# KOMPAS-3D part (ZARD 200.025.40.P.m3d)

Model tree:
1. Поверхность без истории:1
2. Поверхность без истории:2
3. Поверхность без истории:3
4. Поверхность без истории:4
5. Поверхность без истории:5
6. Поверхность без истории:6
7. Поверхность без истории:7
8. Поверхность без истории:8
9. Поверхность без истории:9
10. Поверхность без истории:10
11. Поверхность без истории:11
12. Поверхность без истории:12
13. Поверхность без истории:13
14. Поверхность без истории:14
15. Поверхность без истории:15
16. Поверхность без истории:16
17. Поверхность без истории:17
18. Поверхность без истории:18
19. Поверхность без истории:19
20. Поверхность без истории:20
21. Поверхность без истории:21
22. Поверхность без истории:22
23. Поверхность без истории:23
24. Поверхность без истории:24
25. Поверхность без истории:25
26. Поверхность без истории:26
27. Поверхность без истории:27
28. Поверхность без истории:28
29. Поверхность без истории:29
30. Поверхность без истории:30
31. Поверхность без истории:31
32. Поверхность без истории:32
33. Поверхность без истории:33
34. Поверхность без истории:34
35. Поверхность без истории:35
36. Поверхность без истории:36
37. Поверхность без истории:37
38. Поверхность без истории:38
39. Поверхность без истории:39
40. Поверхность без истории:40
41. Поверхность без истории:41
42. Поверхность без истории:42
43. Поверхность без истории:43
44. Поверхность без истории:44
45. Поверхность без истории:45
46. Поверхность без истории:46
47. Поверхность без истории:47
48. Поверхность без истории:48
49. Поверхность без истории:49
50. Поверхность без истории:50
51. Поверхность без истории:51
52. Поверхность без истории:52
53. Поверхность без истории:53
54. Поверхность без истории:54
55. Поверхность без истории:55
56. Поверхность без истории:56
57. Поверхность без истории:57
58. Поверхность без истории:58
59. Поверхность без истории:59
60. Поверхность без истории:60
61. Поверхность без истории:61
62. Поверхность без истории:62
63. Поверхность без истории:63
64. Поверхность без истории:64
65. Поверхность без истории:65
66. Поверхность без истории:66
67. Поверхность без истории:67
68. Поверхность без истории:68
69. Поверхность без истории:69
70. Поверхность без истории:70
71. Поверхность без истории:71
72. Поверхность без истории:72
73. Поверхность без истории:73
74. Поверхность без истории:74
75. Поверхность без истории:75
76. Поверхность без истории:76
77. Поверхность без истории:77
78. Поверхность без истории:78
79. Поверхность без истории:79
80. Поверхность без истории:80
81. Поверхность без истории:81
82. Поверхность без истории:82
83. Поверхность без истории:83
84. Поверхность без истории:84
85. Поверхность без истории:85
86. Поверхность без истории:86
87. Поверхность без истории:87
88. Поверхность без истории:88
89. Поверхность без истории:89
90. Поверхность без истории:90
91. Поверхность без истории:91
92. Поверхность без истории:92
93. Поверхность без истории:93
94. Поверхность без истории:94
95. Поверхность без истории:95
96. Поверхность без истории:96
97. Поверхность без истории:97
98. Поверхность без истории:98
99. Поверхность без истории:99
100. Поверхность без истории:100
101. Поверхность без истории:101

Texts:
  ЗАРД 200-025-40-Р(АВ880) КП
